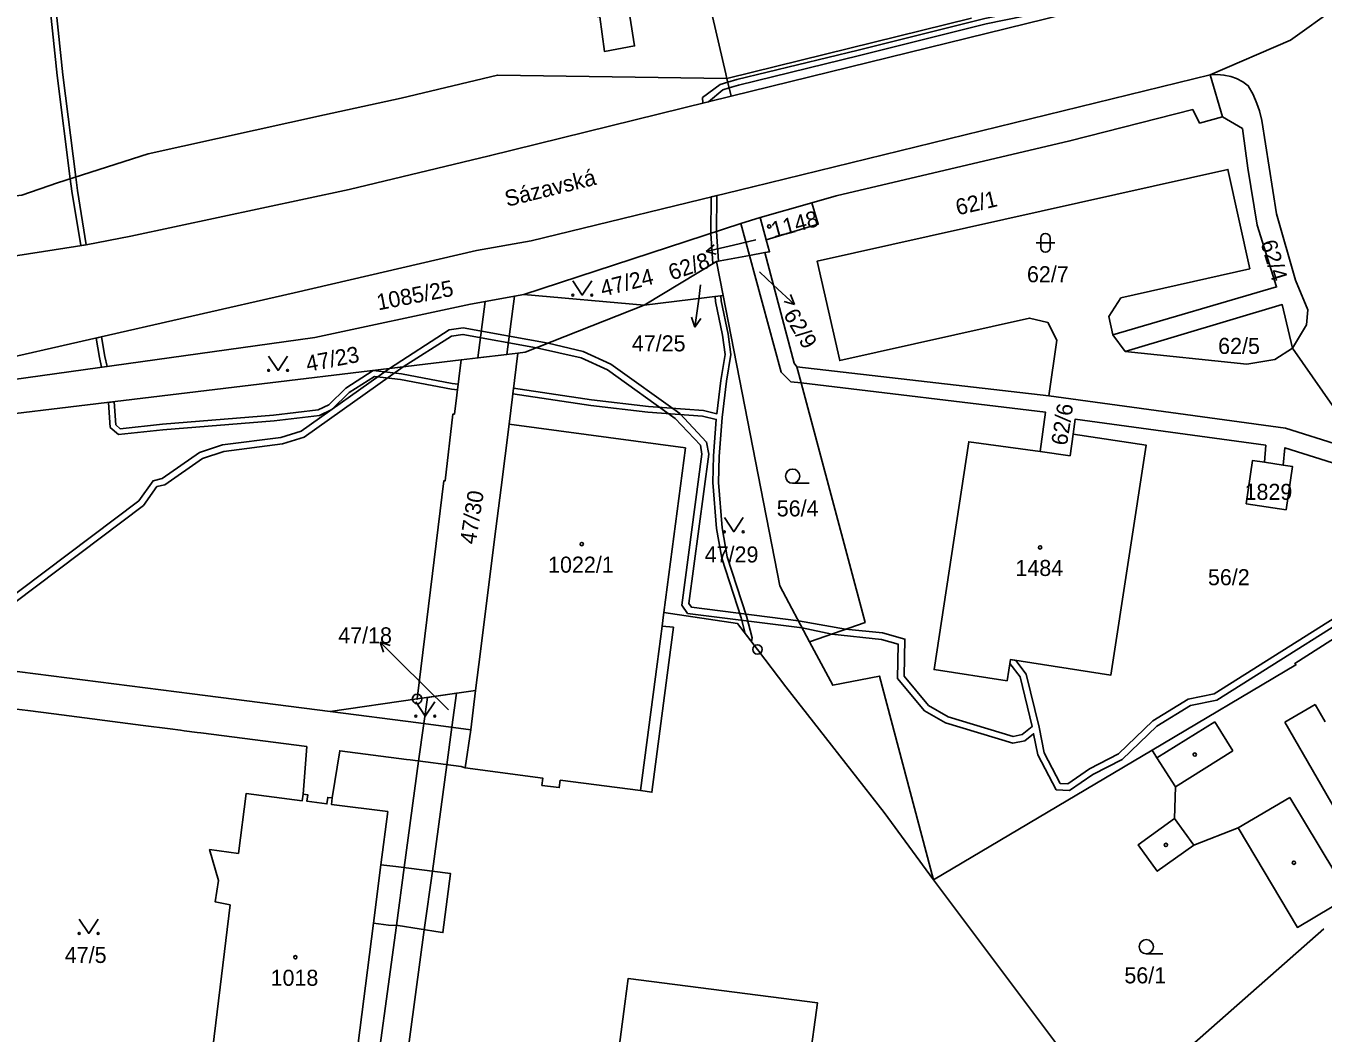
# Model space of a CAD drawing. Extents: x -680203 to -673936, y -1102717 to -1093650.
# Drawn here: x -678978 to -678840.6, y -1098657.2 to -1098550.5 of the extents above; entities that cross this region are included whole.
import ezdxf

# ---------------------------------------------------------------- set-up
doc = ezdxf.new("R2010")
doc.units = 0
for name, color, linetype in [('SOxx02xx_Koleje_param další_Popis10', 7, 'Continuous'), ('SOxx02xx_Staničení_Popis10', 7, 'Continuous'), ('SOxxxxxx_Koleje_hlavní_body_Popis10', 7, 'Continuous'), ('SOxxxxxx_Koleje_LN_parametry_Popis10', 7, 'Continuous'), ('SOxxxxxx_Koleje_param další_Popis10', 7, 'Continuous'), ('SOxxxxxx_Osa_bod_P', 7, 'Continuous'), ('SOxxxxxx_Staničení_Popis10', 7, 'Continuous'), ('x_prac', 7, 'Continuous')]:
    doc.layers.add(name, color=color, linetype=linetype)

msp = doc.modelspace()

# ---------------------------------------------------------------- linework, layer by layer
at = {"layer": 'SOxx02xx_Koleje_param další_Popis10'}
for centre, radius in [((-678900.51, -1098616.55), 0.5), ((-678900.51, -1098616.55), 0.0303), ((-678936.56, -1098621.8), 0.5), ((-678936.56, -1098621.8), 0.0303)]:
    msp.add_circle(centre, radius, dxfattribs=at)
at = {"layer": 'SOxx02xx_Staničení_Popis10'}
for p, q in [((-678905.95, -1098574.41), (-678905.09, -1098573.69)), ((-678903.03, -1098573.73), (-678905.95, -1098574.41)), ((-678900.69, -1098573.17), (-678903.03, -1098573.73)), ((-678905.95, -1098574.41), (-678904.87, -1098574.67)), ((-678900.29, -1098576.55), (-678898.79, -1098577.96)), ((-678906.53, -1098577.94), (-678906.73, -1098579.44)), ((-678898.79, -1098577.96), (-678896.59, -1098580.01)), ((-678906.73, -1098579.44), (-678907.15, -1098582.41)), ((-678896.59, -1098580.01), (-678897.67, -1098579.69)), ((-678896.59, -1098580.01), (-678896.99, -1098578.96)), ((-678907.15, -1098582.41), (-678907.5, -1098581.35)), ((-678907.15, -1098582.41), (-678906.51, -1098581.49)), ((-678938.36, -1098617.9), (-678940.48, -1098615.78)), ((-678940.48, -1098615.78), (-678939.42, -1098616.13)), ((-678940.48, -1098615.78), (-678940.13, -1098616.84)), ((-678933.22, -1098622.96), (-678938.36, -1098617.9))]:
    msp.add_line(p, q, dxfattribs=at)
at = {"layer": 'SOxxxxxx_Koleje_hlavní_body_Popis10'}
for p, q in [((-678871, -1098573.48), (-678869, -1098573.48)), ((-678870.5, -1098572.98), (-678870.5, -1098573.98)), ((-678869.5, -1098573.98), (-678869.5, -1098572.98)), ((-678896.78, -1098598.95), (-678895.03, -1098598.95)), ((-678859.32, -1098648.79), (-678857.57, -1098648.79))]:
    msp.add_line(p, q, dxfattribs=at)
for points in [[(-678920.06, -1098577.52), (-678919.06, -1098579.02), (-678918.06, -1098577.52)], [(-678952.28, -1098585.49), (-678951.28, -1098586.99), (-678950.28, -1098585.49)], [(-678904.01, -1098602.59), (-678903.01, -1098604.09), (-678902.01, -1098602.59)], [(-678936.69, -1098622.11), (-678935.69, -1098623.61), (-678934.69, -1098622.11)], [(-678972.34, -1098645.13), (-678971.34, -1098646.63), (-678970.34, -1098645.13)]]:
    msp.add_lwpolyline(points, dxfattribs=at)
for centre, radius in [((-678920.06, -1098579.02), 0.1), ((-678918.06, -1098579.02), 0.1), ((-678952.28, -1098586.99), 0.1), ((-678950.28, -1098586.99), 0.1), ((-678896.78, -1098598.2), 0.75), ((-678904.01, -1098604.09), 0.1), ((-678902.01, -1098604.09), 0.1), ((-678936.69, -1098623.61), 0.1), ((-678934.69, -1098623.61), 0.1), ((-678972.34, -1098646.63), 0.1), ((-678970.34, -1098646.63), 0.1), ((-678859.32, -1098648.04), 0.75)]:
    msp.add_circle(centre, radius, dxfattribs=at)
for centre, start, end in [((-678870, -1098572.98), 0, 180), ((-678870, -1098573.98), 180, 359.9879)]:
    msp.add_arc(centre, 0.5, start, end, dxfattribs=at)
at = {"layer": 'SOxxxxxx_Koleje_LN_parametry_Popis10'}
for points in [[(-678975.91, -1098543.9), (-678974.67, -1098555.76), (-678973.29, -1098566.7), (-678973.13, -1098568.01), (-678972.17, -1098573.78), (-678971.6, -1098573.69), (-678972.53, -1098567.93), (-678972.71, -1098566.52), (-678974.07, -1098555.7), (-678975.31, -1098543.82)], [(-678832.93, -1098609.16), (-678852.13, -1098621.27), (-678854.88, -1098621.83), (-678858.64, -1098624.13), (-678862.28, -1098627.62), (-678865.33, -1098629.19), (-678867.64, -1098630.79), (-678868.43, -1098630.74), (-678870.15, -1098627.49), (-678870.68, -1098624.78), (-678872.05, -1098619.16), (-678873.15, -1098617.72), (-678873.71, -1098617.63), (-678873.78, -1098618.05), (-678872.69, -1098619.47), (-678871.42, -1098624.72), (-678872.48, -1098625.57), (-678873.43, -1098625.76), (-678880.32, -1098623.68), (-678882.37, -1098622.5), (-678884.95, -1098619.39), (-678884.89, -1098615.45), (-678887.26, -1098614.81), (-678891.17, -1098614.41), (-678896.17, -1098613.52), (-678907.5, -1098612.07), (-678907.77, -1098611.68), (-678905.67, -1098595.86), (-678905.9, -1098594.58), (-678908.74, -1098591.55), (-678916.04, -1098586.33), (-678918.96, -1098585), (-678922.66, -1098584.1), (-678923.91, -1098584.59), (-678919.19, -1098585.66), (-678916.39, -1098586.94), (-678909.21, -1098592.08), (-678906.55, -1098594.9), (-678906.38, -1098595.88), (-678908.5, -1098611.86), (-678907.9, -1098612.73), (-678895.76, -1098614.28), (-678892.62, -1098614.92), (-678887.38, -1098615.5), (-678885.6, -1098615.98), (-678885.66, -1098619.64), (-678882.82, -1098623.04), (-678880.6, -1098624.32), (-678873.47, -1098626.48), (-678872.18, -1098626.23), (-678871.26, -1098625.49), (-678870.82, -1098627.73), (-678868.86, -1098631.42), (-678867.44, -1098631.5), (-678864.97, -1098629.79), (-678861.87, -1098628.2), (-678858.21, -1098624.69), (-678854.62, -1098622.5), (-678851.86, -1098621.93), (-678832.48, -1098609.71)], [(-678985.94, -1098616.66), (-678965.54, -1098601.29), (-678964.11, -1098599.31), (-678963.26, -1098599.11), (-678959.3, -1098596.32), (-678957.02, -1098595.57), (-678950.82, -1098594.79), (-678948.51, -1098594.07), (-678938.03, -1098586.62), (-678939.49, -1098586.8), (-678948.82, -1098593.43), (-678950.97, -1098594.1), (-678957.18, -1098594.89), (-678959.61, -1098595.69), (-678963.55, -1098598.46), (-678964.52, -1098598.69), (-678966.04, -1098600.8), (-678986.13, -1098615.93)], [(-678937.72, -1098660.49), (-678935.79, -1098646.24), (-678934.94, -1098640.05), (-678933.41, -1098628.76), (-678932.87, -1098624.79), (-678932.38, -1098621.19), (-678935.47, -1098621.64), (-678935.85, -1098624.41), (-678936.39, -1098628.37), (-678937.92, -1098639.66), (-678938.75, -1098645.79), (-678941.46, -1098665.71)]]:
    msp.add_lwpolyline(points, dxfattribs=at)
for points in [[(-678868.29, -1098548.67), (-678868.41, -1098548.09), (-678876.41, -1098549.71), (-678889.85, -1098553.07), (-678902.68, -1098556.2), (-678903.63, -1098556.48), (-678904.45, -1098556.72), (-678906.32, -1098558.1), (-678906.3, -1098558.7), (-678905.7, -1098558.55), (-678904.17, -1098557.26), (-678903.49, -1098557.06), (-678902.52, -1098556.78), (-678889.71, -1098553.65), (-678876.27, -1098550.29)], [(-678904.63, -1098575.41), (-678904.84, -1098572.29), (-678904.8, -1098568.47), (-678905.39, -1098568.61), (-678905.43, -1098572.49), (-678905.22, -1098575.67), (-678904.85, -1098575.45)], [(-678929.33, -1098579.7), (-678930.12, -1098585.67), (-678927.05, -1098585.3), (-678926.22, -1098579.13)], [(-678904.99, -1098579.17), (-678904.95, -1098579.71), (-678904.21, -1098583.25), (-678903.93, -1098585.31), (-678904.37, -1098588.07), (-678904.8, -1098591.59), (-678906.22, -1098591.25), (-678912.05, -1098590.82), (-678918.07, -1098590.1), (-678926.34, -1098588.86), (-678926.41, -1098589.46), (-678918.15, -1098590.7), (-678912.11, -1098591.42), (-678906.32, -1098591.85), (-678904.86, -1098592.19), (-678905.16, -1098596.06), (-678905.24, -1098598.88), (-678904.83, -1098603.75), (-678904.29, -1098606.88), (-678902.23, -1098613.19), (-678901.81, -1098614.85), (-678901.15, -1098615.72), (-678901.07, -1098615.31), (-678901.65, -1098613.03), (-678903.71, -1098606.74), (-678904.23, -1098603.67), (-678904.64, -1098598.86), (-678904.56, -1098596.1), (-678904.24, -1098591.99), (-678903.77, -1098588.15), (-678903.33, -1098585.31), (-678903.61, -1098583.15), (-678904.35, -1098579.63), (-678904.39, -1098579.09)], [(-678969.97, -1098586.65), (-678969.38, -1098586.57), (-678969.63, -1098585.52), (-678969.97, -1098583.43), (-678970.55, -1098583.57), (-678970.21, -1098585.64)], [(-678933.16, -1098582.7), (-678939.49, -1098586.8), (-678938.03, -1098586.62), (-678932.91, -1098583.37), (-678931.7, -1098583.19), (-678923.91, -1098584.59), (-678922.66, -1098584.1), (-678931.69, -1098582.48)], [(-678932.27, -1098589.04), (-678932.19, -1098588.44), (-678932.83, -1098588.4), (-678938.2, -1098587.36), (-678941.2, -1098587), (-678944.12, -1098588.87), (-678945.92, -1098590.65), (-678947.04, -1098591.18), (-678951.75, -1098591.75), (-678963.53, -1098592.7), (-678967.99, -1098593.18), (-678968.47, -1098592.75), (-678968.65, -1098590.31), (-678969.25, -1098590.38), (-678969.05, -1098593.03), (-678968.19, -1098593.8), (-678963.47, -1098593.3), (-678951.69, -1098592.35), (-678946.88, -1098591.76), (-678945.58, -1098591.15), (-678943.74, -1098589.35), (-678941.06, -1098587.63), (-678938.3, -1098587.96), (-678932.91, -1098589)]]:
    msp.add_lwpolyline(points, close=True, dxfattribs=at)
at = {"layer": 'SOxxxxxx_Koleje_param další_Popis10'}
for centre in [(-678899.26, -1098571.75), (-678919.12, -1098605.39), (-678870.57, -1098605.75), (-678854.19, -1098627.68), (-678857.24, -1098637.25), (-678843.69, -1098639.14), (-678949.45, -1098649.15)]:
    msp.add_circle(centre, 0.175, dxfattribs=at)
at = {"layer": 'SOxxxxxx_Staničení_Popis10'}
for p, q in [((-678910.6, -1098614.08), (-678911.13, -1098618.1)), ((-678911.13, -1098618.1), (-678912.88, -1098631.51)), ((-678844.65, -1098624.27), (-678841.44, -1098622.38)), ((-678841.44, -1098622.38), (-678840.37, -1098624.21)), ((-678858.19, -1098628.02), (-678852.05, -1098624.21)), ((-678852.05, -1098624.21), (-678850.14, -1098627.28)), ((-678837.78, -1098636.12), (-678844.65, -1098624.27)), ((-678850.14, -1098627.28), (-678856.22, -1098631.12)), ((-678849.57, -1098635.43), (-678844.12, -1098632.22)), ((-678844.12, -1098632.22), (-678837.81, -1098642.73)), ((-678856.33, -1098634.47), (-678854.3, -1098637.27)), ((-678940.38, -1098639.35), (-678941.17, -1098645.54))]:
    msp.add_line(p, q, dxfattribs=at)
at = {"layer": 'x_prac'}
for p, q in [((-678903.73, -1098556.07), (-678877.83, -1098549.69)), ((-678903.28, -1098557.95), (-678903.73, -1098556.07)), ((-678851.24, -1098560.15), (-678852.54, -1098555.7)), ((-678900.23, -1098570.79), (-678894.74, -1098569.24)), ((-678902.26, -1098571.45), (-678925.26, -1098578.96)), ((-678902.26, -1098571.45), (-678900.23, -1098570.79)), ((-678901.35, -1098574.82), (-678902.26, -1098571.45)), ((-678900.23, -1098570.79), (-678899.58, -1098573.15)), ((-678912.49, -1098580.1), (-678904.85, -1098575.45)), ((-678901.35, -1098574.82), (-678904.85, -1098575.45)), ((-678904.85, -1098575.45), (-678904.14, -1098579.06)), ((-678901.35, -1098574.82), (-678899.72, -1098574.52)), ((-678912.49, -1098580.1), (-678925.26, -1098578.96)), ((-678912.49, -1098580.1), (-678904.14, -1098579.06)), ((-678898.14, -1098609.81), (-678904.14, -1098579.06)), ((-678862.88, -1098583.23), (-678861.56, -1098584.99)), ((-678931.87, -1098585.88), (-678925.89, -1098585.16)), ((-678925.89, -1098585.16), (-678926.8, -1098592.7)), ((-678835.26, -1098596.94), (-678843.83, -1098584.64)), ((-678932.6, -1098591.64), (-678931.87, -1098585.88)), ((-678896.33, -1098586.62), (-678869.64, -1098589.68)), ((-678895.88, -1098588.32), (-678896.33, -1098586.62)), ((-678844.82, -1098597.03), (-678846.81, -1098596.73)), ((-678894.98, -1098615.75), (-678898.14, -1098609.81)), ((-678936.56, -1098621.8), (-678930.36, -1098620.9)), ((-678930.36, -1098620.9), (-678930.88, -1098625.05)), ((-678945.76, -1098623.14), (-678936.56, -1098621.8)), ((-678931.47, -1098629.1), (-678930.88, -1098625.05)), ((-678858.7, -1098627.22), (-678881.86, -1098640.97)), ((-678867.97, -1098659.45), (-678881.86, -1098640.97)), ((-678840.5, -1098646.14), (-678863.08, -1098666.02))]:
    msp.add_line(p, q, dxfattribs=at)
for points in [[(-678958.6, -1098519.09), (-678962.01, -1098518.67), (-678963.17, -1098528.04), (-678965.83, -1098527.79), (-678968.09, -1098527.58), (-678969.64, -1098541.15), (-678960.75, -1098542.18), (-678961.02, -1098544.49), (-678921.63, -1098549.03), (-678917.2, -1098549.55), (-678916.71, -1098553.2), (-678913.51, -1098552.63), (-678914.01, -1098549.49), (-678913.84, -1098547.59), (-678914.17, -1098547.56), (-678913.64, -1098543.29), (-678911.4, -1098524.86), (-678911.22, -1098523.39), (-678958.42, -1098517.62), (-678958.6, -1098519.09)], [(-678903.73, -1098556.07), (-678903.84, -1098555.58), (-678906.93, -1098542.34), (-678905.97, -1098531.42), (-678903.7, -1098529.13), (-678901.1, -1098528.43)], [(-678840.17, -1098537.37), (-678842.98, -1098539.45), (-678847.97, -1098542.81), (-678850.89, -1098544.36), (-678852.34, -1098544.98), (-678857.43, -1098546.64), (-678861.63, -1098547.66), (-678903.28, -1098557.95)], [(-678852.54, -1098555.7), (-678844.04, -1098552.03), (-678839.22, -1098548.55)], [(-679040.29, -1098588.41), (-679024.16, -1098588.32), (-679008.67, -1098587.65), (-678982.12, -1098586.21), (-678949.56, -1098578.77), (-678930.27, -1098574.3), (-678924.48, -1098573.28), (-678901, -1098567.54), (-678852.54, -1098555.7)], [(-679024.26, -1098573.29), (-678978.43, -1098568.45), (-678974.63, -1098567.13), (-678965.05, -1098564.07), (-678946.36, -1098559.94), (-678938.23, -1098558.15), (-678928.04, -1098555.71), (-678903.73, -1098556.07)], [(-678847.09, -1098560.53), (-678847.34, -1098559.51), (-678847.6, -1098558.72), (-678848.01, -1098557.76), (-678848.52, -1098556.84), (-678849.11, -1098556.42), (-678849.76, -1098556.09), (-678850.38, -1098555.86), (-678851.09, -1098555.71), (-678851.82, -1098555.66), (-678852.54, -1098555.7)], [(-678903.28, -1098557.95), (-678928.91, -1098564.28), (-678943.76, -1098567.85), (-678966.88, -1098572.76), (-678971.6, -1098573.69), (-678982.27, -1098575.37), (-678989.19, -1098576.65), (-679006.16, -1098578.84), (-679015.52, -1098579.01), (-679023.33, -1098579.28), (-679037.21, -1098579.21), (-679042.25, -1098579.5), (-679050.47, -1098579.2), (-679077.53, -1098577.77), (-679090.67, -1098576.96), (-679104.61, -1098575.94), (-679131.51, -1098574.1), (-679132.75, -1098574.02), (-679142.38, -1098573.41), (-679180.81, -1098570.47), (-679213.51, -1098568.04), (-679217.22, -1098567.74), (-679219.83, -1098567.51)], [(-678894.74, -1098569.24), (-678892.17, -1098568.51), (-678867.4, -1098562.68), (-678854.39, -1098559.37), (-678853.68, -1098560.8), (-678851.24, -1098560.15)], [(-678862.88, -1098583.23), (-678845.52, -1098578.16), (-678847.58, -1098571.6), (-678848.58, -1098565.56), (-678849.12, -1098561.39), (-678851.24, -1098560.15)], [(-678843.83, -1098584.64), (-678842.34, -1098582.18), (-678842.2, -1098580.59), (-678843.51, -1098577.44), (-678845.51, -1098570.41), (-678847.09, -1098560.53)], [(-678869.64, -1098589.68), (-678868.8, -1098583.78), (-678869.74, -1098581.93), (-678871.7, -1098581.46), (-678891.79, -1098585.96), (-678894.19, -1098575.44), (-678850.67, -1098565.71), (-678848.36, -1098576.22), (-678862, -1098579.31), (-678863.28, -1098581.27), (-678862.88, -1098583.23)], [(-678899.58, -1098573.15), (-678894.06, -1098571.51), (-678894.74, -1098569.24)], [(-678899.58, -1098573.15), (-678899.22, -1098574.43), (-678899.72, -1098574.52)], [(-678895.88, -1098588.32), (-678896.96, -1098588.19), (-678898.01, -1098587.19), (-678901.35, -1098574.82)], [(-678899.72, -1098574.52), (-678896.61, -1098586.24), (-678896.33, -1098586.62)], [(-678925.26, -1098578.96), (-678930.89, -1098579.98), (-678947.39, -1098583.5), (-679008.4, -1098592.01), (-679023.02, -1098593.15)], [(-678925.89, -1098585.16), (-678925.12, -1098585.07), (-678912.49, -1098580.1)], [(-678861.56, -1098584.99), (-678844.92, -1098580.03), (-678843.83, -1098584.64)], [(-678861.56, -1098584.99), (-678848.67, -1098586.33), (-678845.69, -1098585.84), (-678843.83, -1098584.64)], [(-678931.87, -1098585.88), (-678991.72, -1098593.09), (-679023.02, -1098593.15)], [(-678894.98, -1098615.75), (-678889.11, -1098613.69), (-678895.88, -1098588.32)], [(-678870.57, -1098595.59), (-678869.98, -1098591.42), (-678895.88, -1098588.32)], [(-678869.64, -1098589.68), (-678844.57, -1098593.1), (-678838.74, -1098594.96), (-678835.26, -1098596.94)], [(-678936.56, -1098621.8), (-678933.71, -1098598.69), (-678933.58, -1098598.69), (-678932.76, -1098591.63), (-678932.6, -1098591.64)], [(-678930.36, -1098620.9), (-678930.01, -1098618.16), (-678928.2, -1098603.79), (-678927.64, -1098599.41), (-678926.8, -1098592.7)], [(-678926.8, -1098592.7), (-678908.13, -1098595.2), (-678910.43, -1098612.64)], [(-678846.81, -1098596.73), (-678846.66, -1098594.93), (-678866.85, -1098592.16), (-678867.05, -1098593.76)], [(-678870.57, -1098595.59), (-678878.13, -1098594.55), (-678881.79, -1098618.68), (-678874.06, -1098619.87), (-678873.71, -1098617.63), (-678863.07, -1098619.27), (-678859.32, -1098594.92), (-678867.05, -1098593.76)], [(-678867.05, -1098593.76), (-678867.39, -1098596.03), (-678870.57, -1098595.59)], [(-678835.7, -1098599.68), (-678836.45, -1098598.62), (-678839.61, -1098596.8), (-678844.64, -1098595.19), (-678844.82, -1098597.03)], [(-678846.81, -1098596.73), (-678848.08, -1098596.54), (-678848.74, -1098601.12), (-678844.52, -1098601.75), (-678843.83, -1098597.18), (-678844.82, -1098597.03)], [(-678830.89, -1098609.91), (-678843.57, -1098618.04), (-678843.47, -1098618.19), (-678858.7, -1098627.22)], [(-678945.76, -1098623.14), (-678960.39, -1098621.26), (-678978.62, -1098618.92), (-679008.09, -1098615.13), (-679026.48, -1098612.77), (-679045.57, -1098610.31), (-679046.14, -1098614.2), (-679043.63, -1098614.52), (-679043.9, -1098619.61)], [(-678931.47, -1098629.1), (-678923.24, -1098630.17), (-678923.34, -1098630.95), (-678921.49, -1098631.19), (-678921.39, -1098630.41), (-678912.88, -1098631.51), (-678911.69, -1098631.67), (-678909.89, -1098617.92), (-678909.4, -1098614.21), (-678910.6, -1098614.08), (-678910.46, -1098612.88), (-678910.43, -1098612.64)], [(-678910.43, -1098612.64), (-678902.6, -1098613.82), (-678900.51, -1098616.55), (-678897.49, -1098620.51), (-678893.94, -1098625.05), (-678887.09, -1098633.82), (-678881.86, -1098640.97)], [(-678894.98, -1098615.75), (-678892.53, -1098620.34), (-678887.59, -1098619.38), (-678881.86, -1098640.97)], [(-678993.18, -1098626.05), (-678992.86, -1098624.14), (-678992.38, -1098621.14), (-678985.52, -1098622.03), (-678985.12, -1098622.08), (-678979.4, -1098622.82), (-678979, -1098622.87), (-678977.8, -1098623.02), (-678975.04, -1098623.38), (-678965.57, -1098624.6), (-678962.71, -1098624.97), (-678961.62, -1098625.11), (-678961.21, -1098625.17), (-678959.86, -1098625.34), (-678959.46, -1098625.39), (-678948.25, -1098626.84), (-678948.62, -1098631.88)], [(-678930.88, -1098625.05), (-678936.41, -1098624.34), (-678945.76, -1098623.14)], [(-678945.55, -1098632.28), (-678944.75, -1098627.29), (-678937.68, -1098628.2), (-678937.28, -1098628.26), (-678931.9, -1098628.95), (-678931.47, -1098629.1)], [(-678858.7, -1098627.22), (-678858.19, -1098628.02), (-678856.22, -1098631.12), (-678856.33, -1098634.47), (-678860.17, -1098637.24), (-678858.15, -1098640.05), (-678854.3, -1098637.27), (-678849.57, -1098635.43), (-678843.31, -1098645.99), (-678837.81, -1098642.73), (-678837.32, -1098643.55)], [(-678948.62, -1098631.88), (-678948.71, -1098632.58), (-678954.66, -1098631.82), (-678955.48, -1098638.15), (-678958.53, -1098637.75), (-678957.59, -1098641.01), (-678957.94, -1098643.3), (-678956.36, -1098643.61), (-678959.12, -1098666.26), (-678954.56, -1098666.86), (-678954.62, -1098667.35), (-678955.13, -1098670.94)], [(-678945.55, -1098632.28), (-678946.01, -1098632.22), (-678946.1, -1098632.91), (-678948.23, -1098632.64), (-678948.14, -1098631.95), (-678948.62, -1098631.88)], [(-678949.19, -1098671.71), (-678948.69, -1098668.13), (-678948.62, -1098667.64), (-678944.07, -1098668.24), (-678943.34, -1098662.57), (-678943.04, -1098660.21), (-678941.17, -1098645.54), (-678939.6, -1098645.76), (-678938.56, -1098645.8), (-678934.12, -1098646.51), (-678933.82, -1098646.55), (-678933.01, -1098640.3), (-678933.31, -1098640.26), (-678938.81, -1098639.55), (-678940.38, -1098639.35), (-678939.67, -1098633.73), (-678945.63, -1098632.97), (-678945.55, -1098632.28)], [(-678896.41, -1098670.24), (-678895.49, -1098663.72), (-678884.63, -1098664.78), (-678884.23, -1098661.35), (-678895.03, -1098660.41), (-678894.13, -1098653.99), (-678914.2, -1098651.41), (-678914.55, -1098654.08), (-678916.32, -1098667.59), (-678896.41, -1098670.24)]]:
    msp.add_lwpolyline(points, dxfattribs=at)

# ---------------------------------------------------------------- texts
at = {"layer": 'SOxx02xx_Staničení_Popis10'}
msp.add_text('Sázavská', height=1.7, rotation=14, dxfattribs=at).set_placement((-678927.03, -1098569.68))
at = {"layer": 'SOxxxxxx_Osa_bod_P'}
for s, rotation, p in [('62/1', 13, (-678879.29, -1098570.58)), ('1148', 15, (-678898.8, -1098572.98)), ('62/4', 287, (-678847.24, -1098573.46)), ('62/8', 19, (-678909.58, -1098577.49)), ('47/24', 14, (-678916.9, -1098579.19)), ('1085/25', 11, (-678940.66, -1098580.64)), ('62/9', 301, (-678897.82, -1098581.09)), ('47/23', 11, (-678948.15, -1098587.16)), ('62/6', 81, (-678867.73, -1098595.02)), ('47/30', 81, (-678930.36, -1098605.49))]:
    msp.add_text(s, height=1.7, rotation=rotation, dxfattribs=at).set_placement(p)
for s, p in [('62/7', (-678871.96, -1098577.66)), ('47/25', (-678913.81, -1098584.98)), ('62/5', (-678851.71, -1098585.25)), ('1829', (-678848.91, -1098600.71)), ('56/4', (-678898.46, -1098602.46)), ('47/29', (-678906.09, -1098607.34)), ('1022/1', (-678922.68, -1098608.42)), ('1484', (-678873.18, -1098608.77)), ('56/2', (-678852.79, -1098609.75)), ('47/18', (-678944.91, -1098615.91)), ('47/5', (-678973.87, -1098649.76)), ('1018', (-678952.07, -1098652.18)), ('56/1', (-678861.64, -1098651.92))]:
    msp.add_text(s, height=1.7, dxfattribs=at).set_placement(p)

doc.saveas('drawing.dxf')
